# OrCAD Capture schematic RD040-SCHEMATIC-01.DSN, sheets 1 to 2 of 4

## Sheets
1 4: size A3
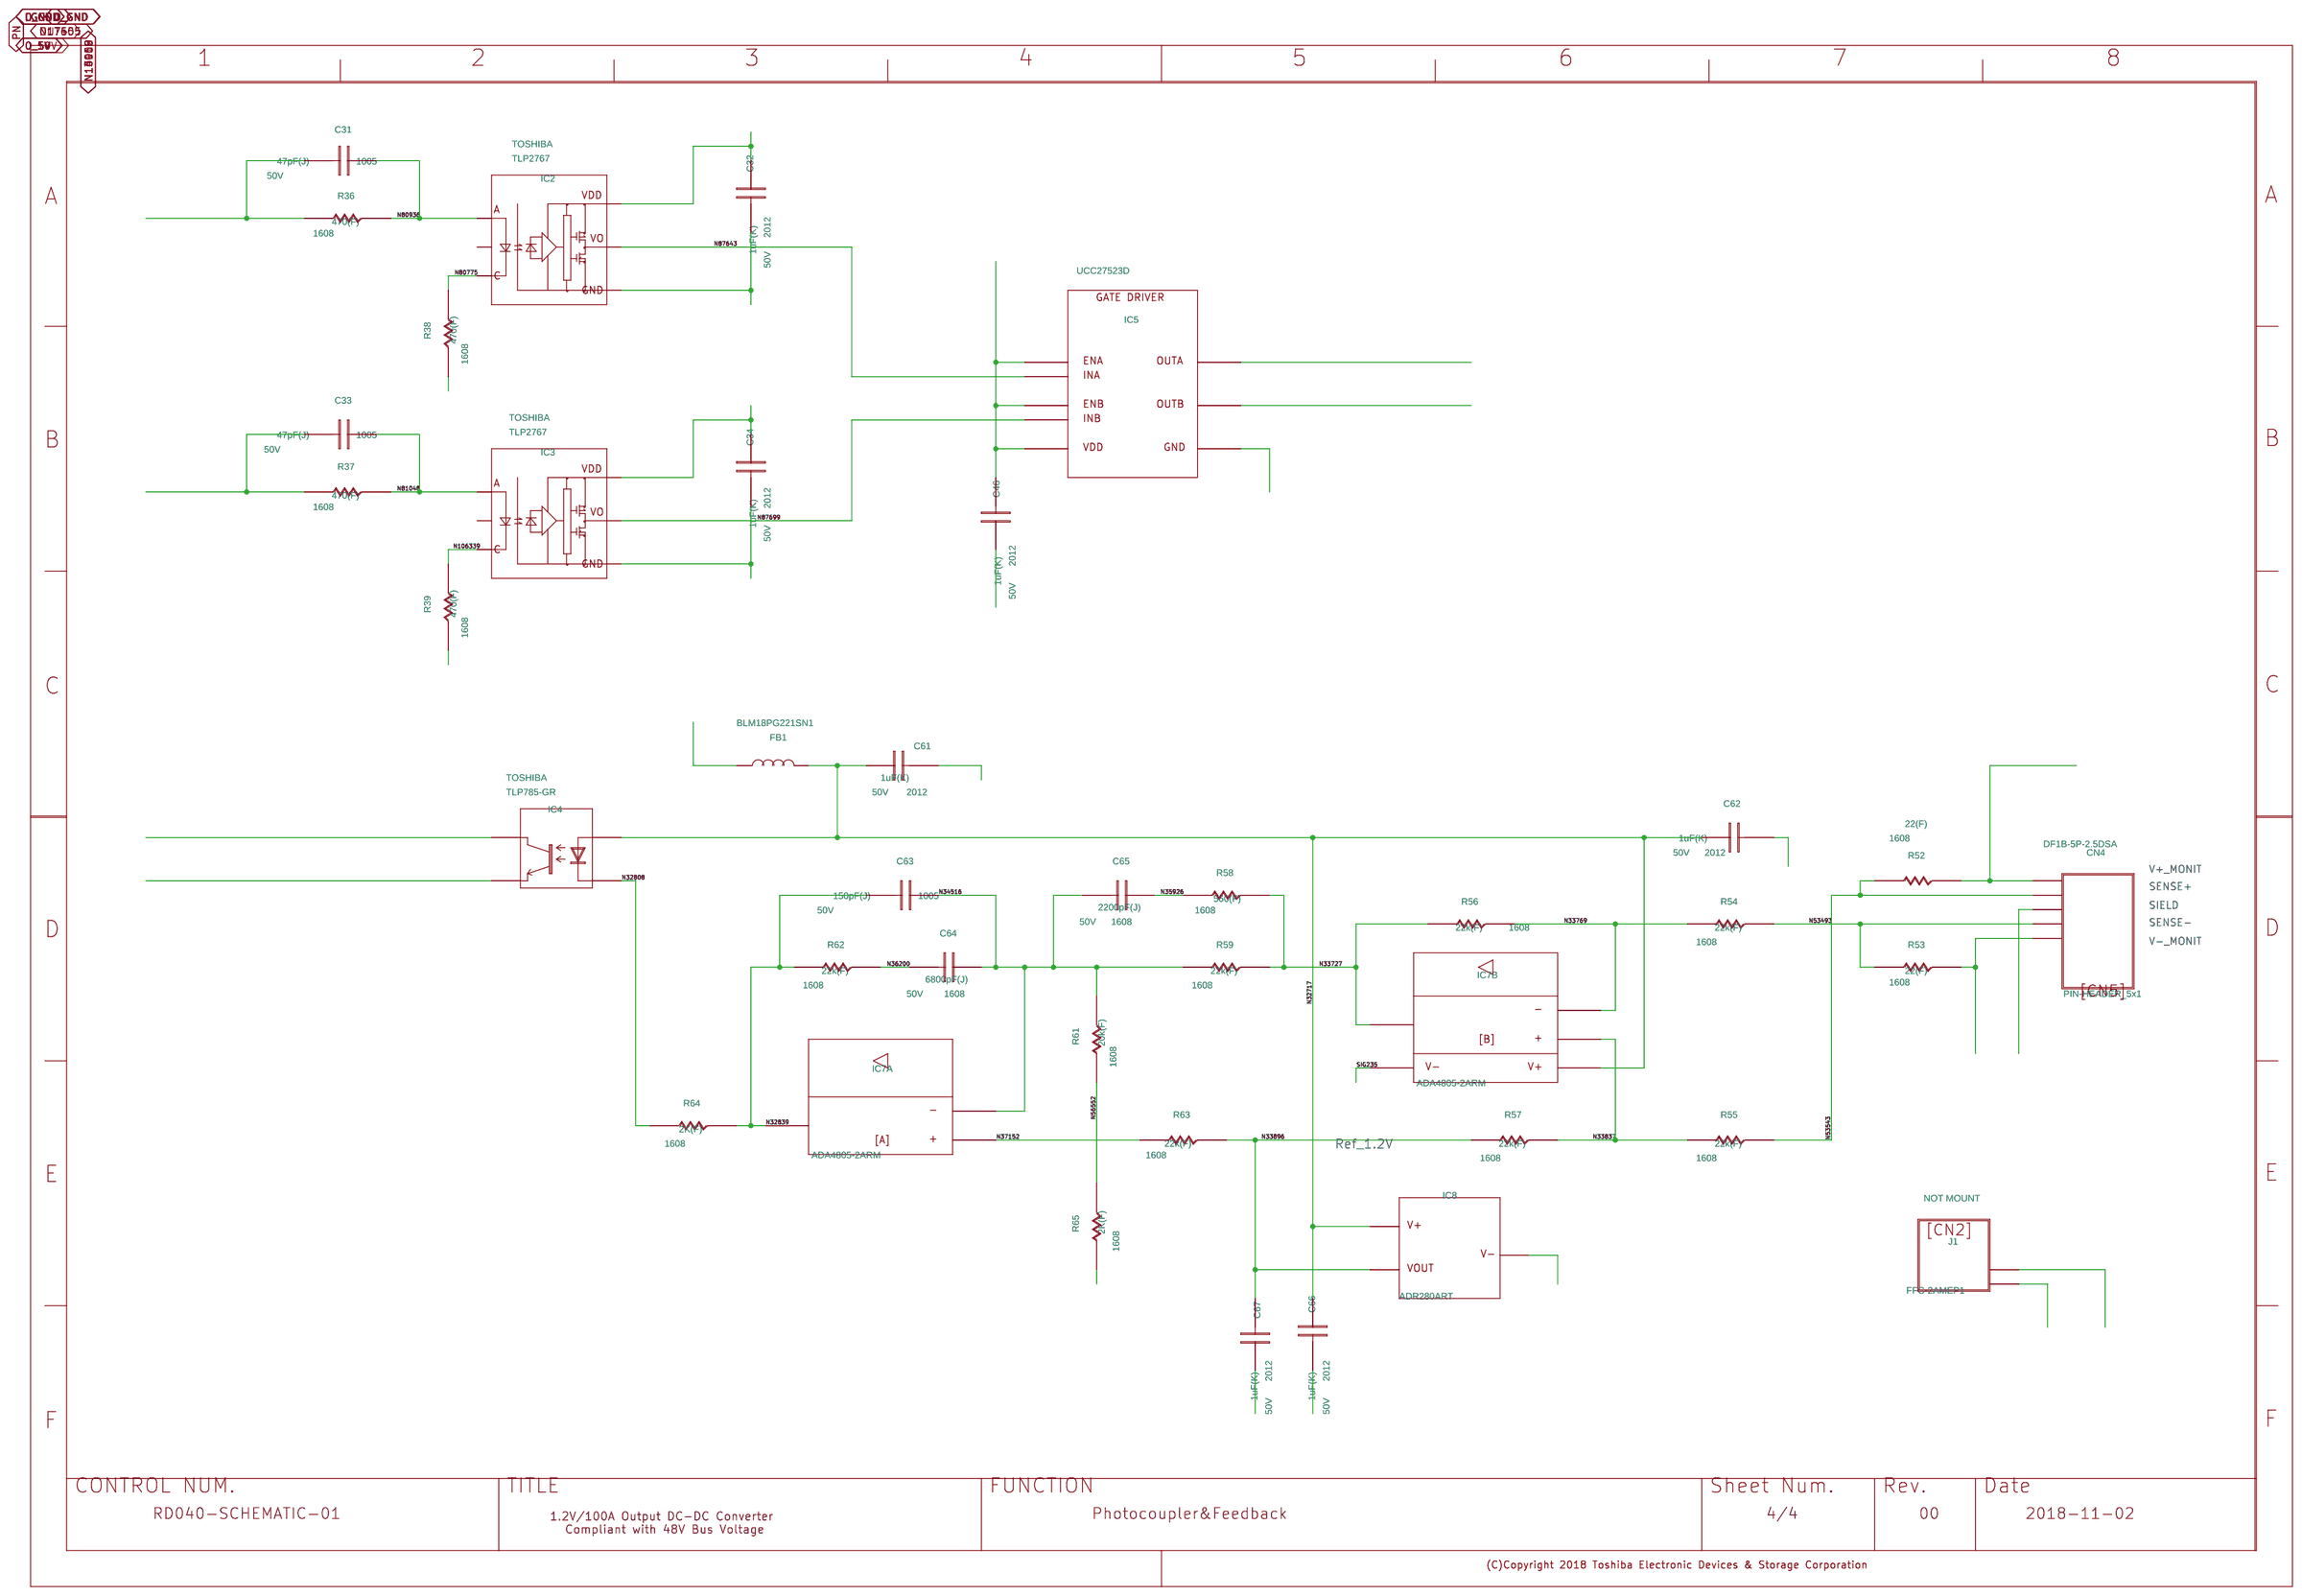
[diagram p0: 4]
2 3: size A3
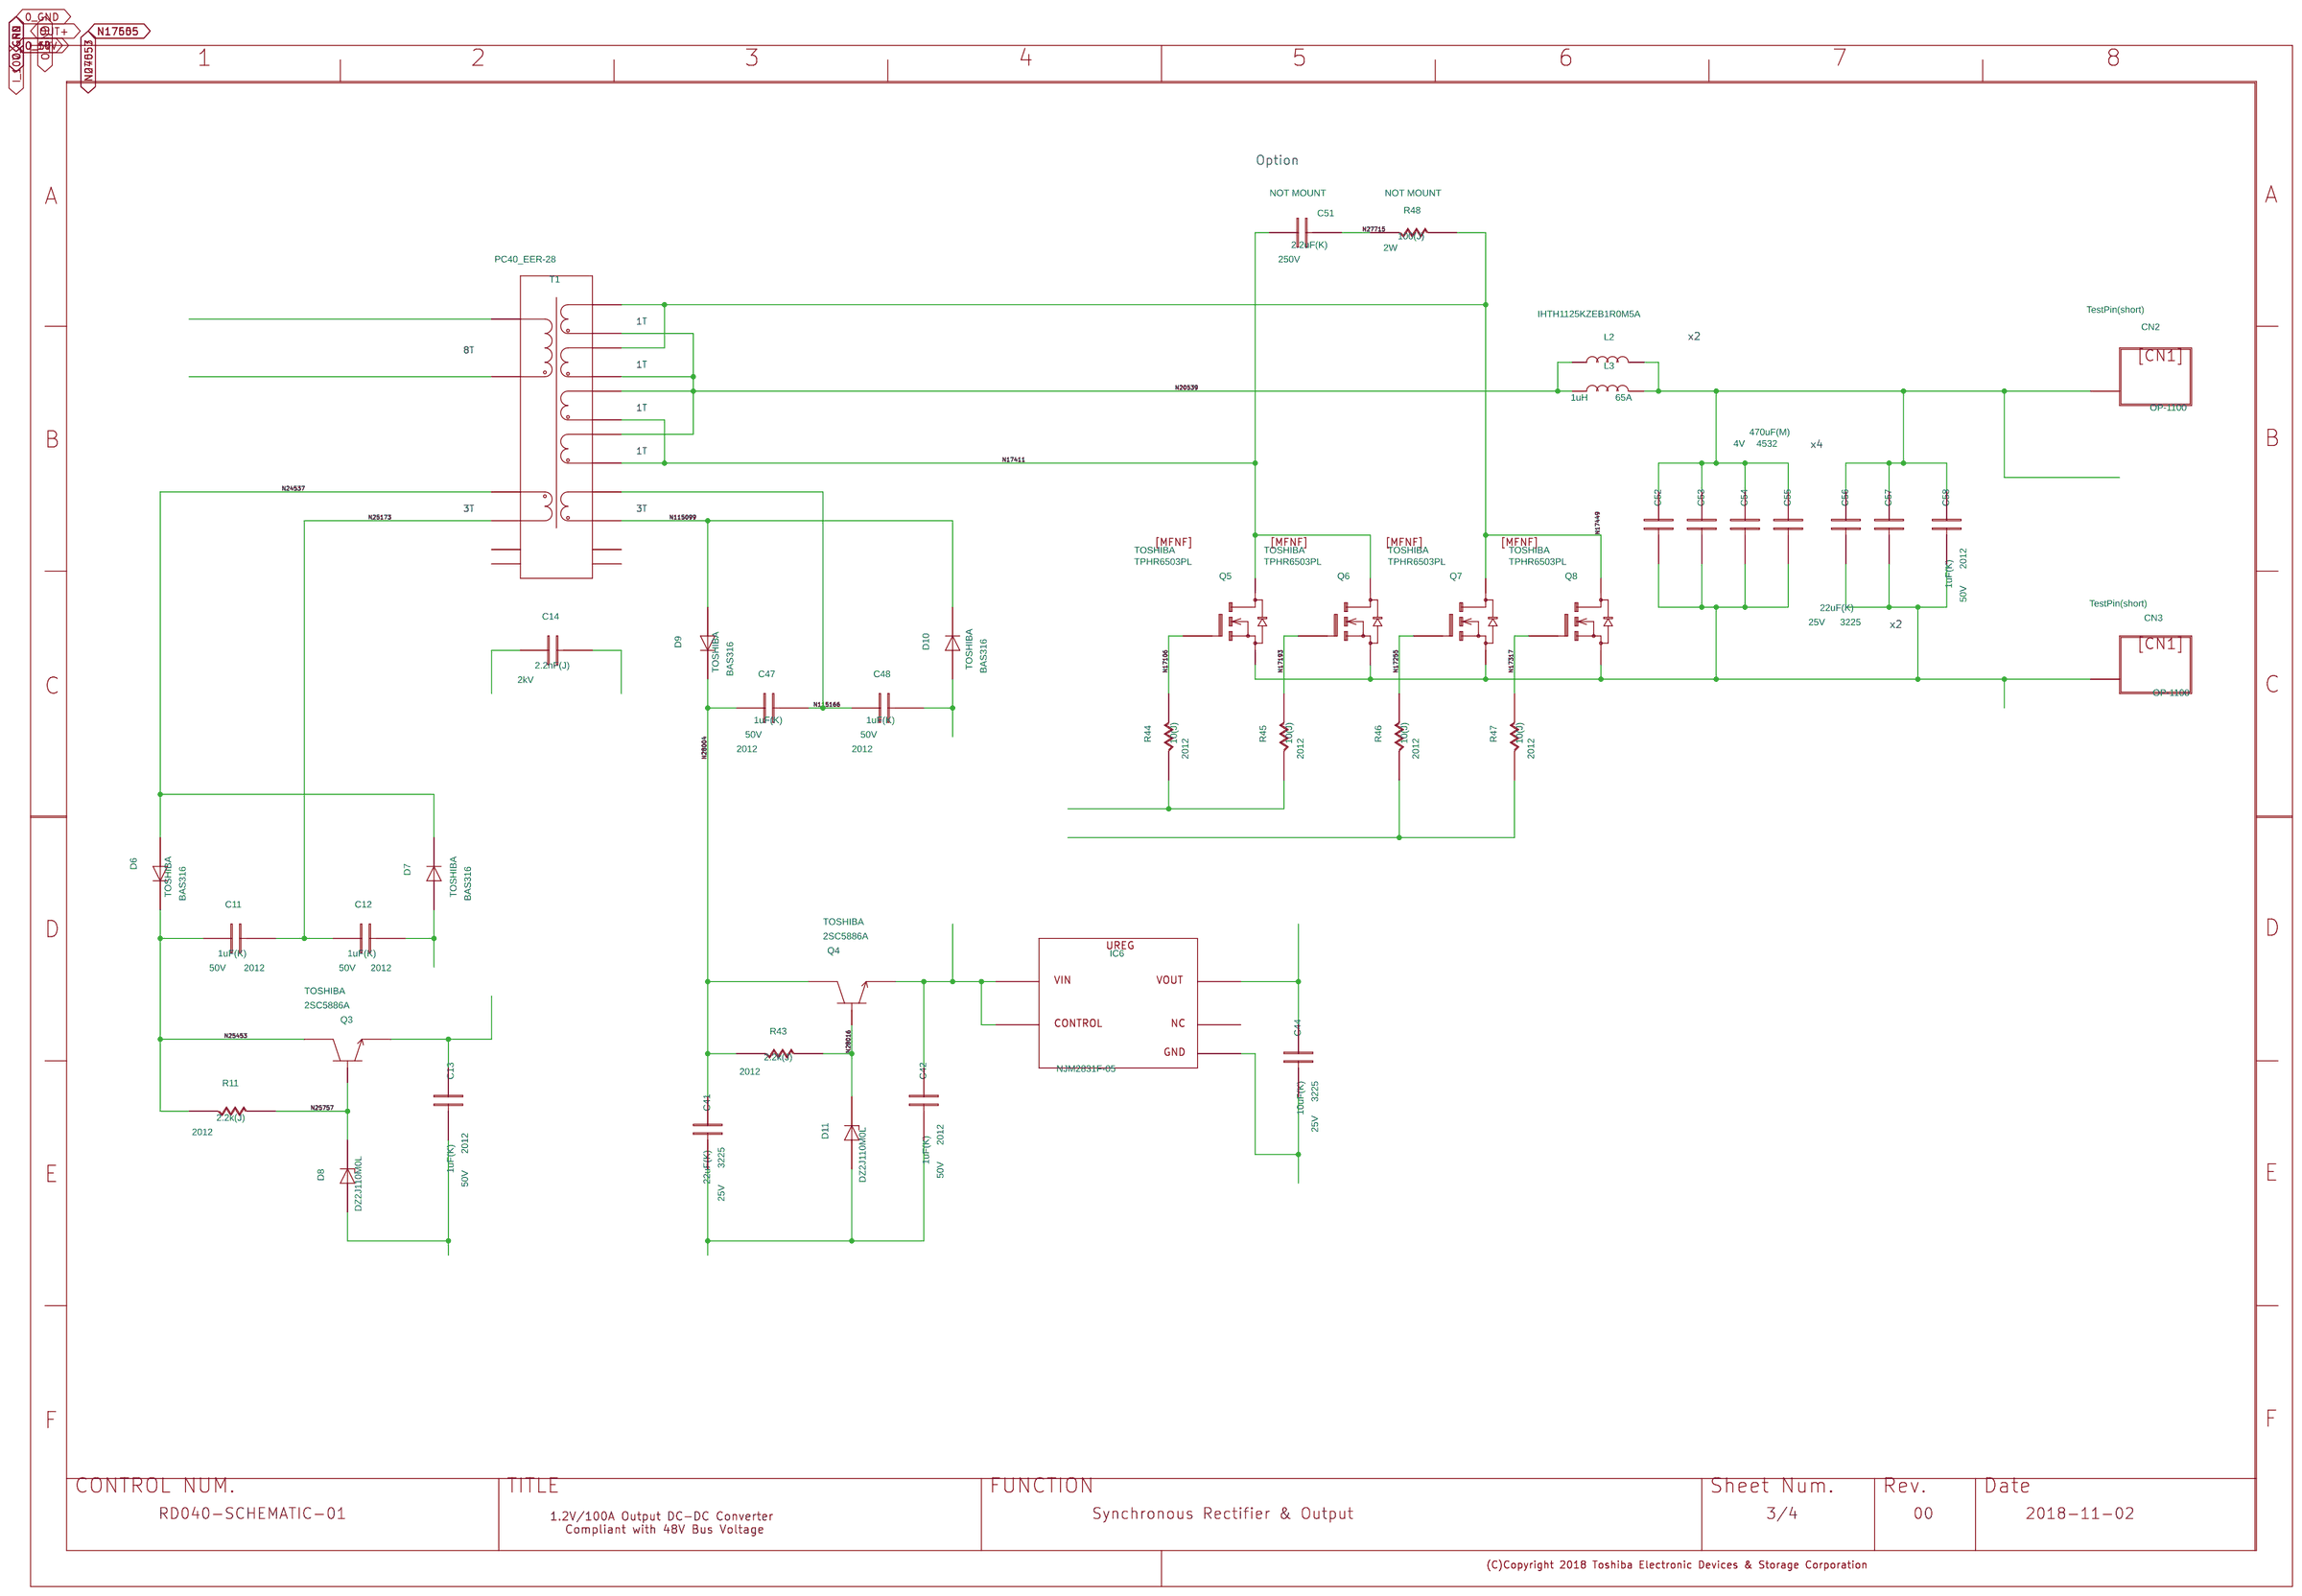
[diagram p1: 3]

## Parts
sheet 3
C11  1uF-K_2012  [CHIP-2012]
C12  1uF-K_2012  [CHIP-2012]
C13  1uF-K_2012  [CHIP-2012]
C14  2200pF-J_2kV  [Radial-2]
C41  22uF-K_3225  [CHIP-3225]
C42  1uF-K_2012  [CHIP-2012]
C44  10uF-K_3225  [CHIP-3225]
C47  1uF-K_2012  [CHIP-2012]
C48  1uF-K_2012  [CHIP-2012]
C51  NM_250V  [Radial-2]
C52  470uF-M_4532  [CHIP-4532]
C53  470uF-M_4532  [CHIP-4532]
C54  470uF-M_4532  [CHIP-4532]
C55  470uF-M_4532  [CHIP-4532]
C56  22uF-K_3225  [CHIP-3225]
C57  22uF-K_3225  [CHIP-3225]
C58  1uF-K_2012  [CHIP-2012]
CN2  OP-1100  [TH-4]
CN3  OP-1100  [TH-4]
D6  BAS316  [CHIP-2012]
D7  BAS316  [CHIP-2012]
D8  DZ2J110M0L  [SC90A]
D9  BAS316  [CHIP-2012]
D10  BAS316  [CHIP-2012]
D11  DZ2J110M0L  [SC90A]
IC6  NJM2831F-05  [SOT23-5]
L2  1uH-M  [RADIAL-2]
L3  1uH-M  [RADIAL-2]
Q3  TRNL
Q4  2SC5886A  [P-MOLD]
Q5  TPHR6503PL  [SO-8]
Q6  TPHR6503PL  [SO-8]
Q7  TPHR6503PL  [SO-8]
Q8  TPHR6503PL  [SO-8]
R11  2k2-J_2012  [CHIP-2012]
R43  2k2-J_2012  [CHIP-2012]
R44  10-J_2012  [CHIP-2012]
R45  10-J_2012  [CHIP-2012]
R46  10-J_2012  [CHIP-2012]
R47  10-J_2012  [CHIP-2012]
R48  NM_2W  [Axial-2]
T1  MAIN-TRANS
U?#1  WAKU_DEF100_2018
sheet 4
C31  47pF-J_1005  [CHIP-1005]
C32  1uF-K_2012  [CHIP-2012]
C33  47pF-J_1005  [CHIP-1005]
C34  1uF-K_2012  [CHIP-2012]
C46  1uF-K_2012  [CHIP-2012]
C61  1uF-K_2012  [CHIP-2012]
C62  1uF-K_2012  [CHIP-2012]
C63  150pF-J_1005  [CHIP-1005]
C64  6800pF-J_1608  [CHIP-1608]
C65  2200pF-J_1608  [CHIP-1608]
C66  1uF-K_2012  [CHIP-2012]
C67  1uF-K_2012  [CHIP-2012]
CN4  DF1B-5P-2.5DSA  [SIP-5]
FB1  BLM18PG221  [CHIP-1608]
IC2  TLP2767  [TSSOP-6]
IC3  TLP2767  [TSSOP-6]
IC4  TLP785-GR  [DIP-4]
IC5  UCC27523D  [SO-8]
IC7  L4805_1  (sections A,B)
IC8  L280
J1  N.M_JUMPER  [SIP-2]
R36  470-F_1608  [CHIP-1608]
R37  470-F_1608  [CHIP-1608]
R38  470-F_1608  [CHIP-1608]
R39  470-F_1608  [CHIP-1608]
R52  22-F_1608  [CHIP-1608]
R53  22-F_1608  [CHIP-1608]
R54  22k-F_1608  [CHIP-1608]
R55  22k-F_1608  [CHIP-1608]
R56  22k-F_1608  [CHIP-1608]
R57  22k-F_1608  [CHIP-1608]
R58  560-F_1608  [CHIP-1608]
R59  22k-F_1608  [CHIP-1608]
R61  20k-F_1608  [CHIP-1608]
R62  22k-F_1608  [CHIP-1608]
R63  22k-F_1608  [CHIP-1608]
R64  2k0-F_1608  [CHIP-1608]
R65  2k0-F_1608  [CHIP-1608]
U?#4  WAKU_DEF100_2018

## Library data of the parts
C11 = C: AUTHOR: w20070dm; COMMENT: Chip-Capacitor(X7R),1uF-K,50V; COMPCOMMENT: 2012; COMPONENTNAME: C_C; COMPONENTTYPE: 4; DATE: 2018/09/12; INSTANCENAME: I25290; MAKER: Murata; NUMBER DEVICES IN PACKAGE: 1; PIN NAMES ROTATE: True; PIN NAMES VISIBLE: False; PIN NUMBERS VISIBLE: False; SAVECOUNT: 1; TIME: 16:59:57; TYPE: GCM21BR71H105K; UPDATEDATE: 2018/09/12; UPDATETIME: 16:59:57; UPDATEUSER: w20070dm; VAL1: 1uF(K); VAL2: 50V; VAL3: GCM21BR71H105K
C12 = C: AUTHOR: w20070dm; COMMENT: Chip-Capacitor(X7R),1uF-K,50V; COMPCOMMENT: 2012; COMPONENTNAME: C_C; COMPONENTTYPE: 4; DATE: 2018/09/12; INSTANCENAME: I25350; MAKER: Murata; NUMBER DEVICES IN PACKAGE: 1; PIN NAMES ROTATE: True; PIN NAMES VISIBLE: False; PIN NUMBERS VISIBLE: False; SAVECOUNT: 1; TIME: 16:59:57; TYPE: GCM21BR71H105K; UPDATEDATE: 2018/09/12; UPDATETIME: 16:59:57; UPDATEUSER: w20070dm; VAL1: 1uF(K); VAL2: 50V; VAL3: GCM21BR71H105K
C13 = C: AUTHOR: w20070dm; COMMENT: Chip-Capacitor(X7R),1uF-K,50V; COMPCOMMENT: 2012; COMPONENTNAME: C_C; COMPONENTTYPE: 4; DATE: 2018/09/12; INSTANCENAME: I29535; MAKER: Murata; NUMBER DEVICES IN PACKAGE: 1; PIN NAMES ROTATE: True; PIN NAMES VISIBLE: False; PIN NUMBERS VISIBLE: False; SAVECOUNT: 1; TIME: 16:59:57; TYPE: GCM21BR71H105K; UPDATEDATE: 2018/09/12; UPDATETIME: 16:59:57; UPDATEUSER: w20070dm; VAL1: 1uF(K); VAL2: 50V; VAL3: GCM21BR71H105K
C14 = C: AUTHOR: w20070dm; COMMENT: Film-Capacitor(PET),2200pF-J,2kVdc; COMPONENTNAME: C_C; COMPONENTTYPE: 4; DATE: 2018/09/12; INSTANCENAME: I20635125; MAKER: Panasonic; NUMBER DEVICES IN PACKAGE: 1; PIN NAMES ROTATE: True; PIN NAMES VISIBLE: False; PIN NUMBERS VISIBLE: False; SAVECOUNT: 1; TIME: 16:59:57; TYPE: ECWH20222JV; UPDATEDATE: 2018/09/12; UPDATETIME: 16:59:57; UPDATEUSER: w20070dm; VAL1: 2.2nF(J); VAL2: 2kV; VAL3: ECWH20222JV
C41 = C: AUTHOR: w20070dm; COMMENT: Chip-Capacitor(X7S),22uF-K,25V; COMPCOMMENT: 3225; COMPONENTNAME: C_C; COMPONENTTYPE: 4; DATE: 2018/09/12; INSTANCENAME: I28285; MAKER: Murata; NUMBER DEVICES IN PACKAGE: 1; PIN NAMES ROTATE: True; PIN NAMES VISIBLE: False; PIN NUMBERS VISIBLE: False; SAVECOUNT: 1; TIME: 16:59:57; TYPE: GRM32ER71E226K; UPDATEDATE: 2018/09/12; UPDATETIME: 16:59:57; UPDATEUSER: w20070dm; VAL1: 22uF(K); VAL2: 25V; VAL3: GRM32ER71E226K
C42 = C: AUTHOR: w20070dm; COMMENT: Chip-Capacitor(X7R),1uF-K,50V; COMPCOMMENT: 2012; COMPONENTNAME: C_C; COMPONENTTYPE: 4; DATE: 2018/09/12; INSTANCENAME: I29753; MAKER: Murata; NUMBER DEVICES IN PACKAGE: 1; PIN NAMES ROTATE: True; PIN NAMES VISIBLE: False; PIN NUMBERS VISIBLE: False; SAVECOUNT: 1; TIME: 16:59:57; TYPE: GCM21BR71H105K; UPDATEDATE: 2018/09/12; UPDATETIME: 16:59:57; UPDATEUSER: w20070dm; VAL1: 1uF(K); VAL2: 50V; VAL3: GCM21BR71H105K
C44 = C: AUTHOR: w20070dm; COMMENT: Chip-Capacitor(X7R),10uF-K,50V; COMPCOMMENT: 3225; COMPONENTNAME: C_C; COMPONENTTYPE: 4; DATE: 2018/09/12; INSTANCENAME: I96322; MAKER: Murata; NUMBER DEVICES IN PACKAGE: 1; PIN NAMES ROTATE: True; PIN NAMES VISIBLE: False; PIN NUMBERS VISIBLE: False; SAVECOUNT: 1; TIME: 16:59:57; TYPE: GCM32ER71H106K; UPDATEDATE: 2018/09/12; UPDATETIME: 16:59:57; UPDATEUSER: w20070dm; VAL1: 10uF(K); VAL2: 25V; VAL3: GCM32ER71E106K
C47 = C: AUTHOR: w20070dm; COMMENT: Chip-Capacitor(X7R),1uF-K,50V; COMPCOMMENT: 2012; COMPONENTNAME: C_C; COMPONENTTYPE: 4; DATE: 2018/09/12; INSTANCENAME: I115041; MAKER: Murata; NUMBER DEVICES IN PACKAGE: 1; PIN NAMES ROTATE: True; PIN NAMES VISIBLE: False; PIN NUMBERS VISIBLE: False; SAVECOUNT: 1; TIME: 16:59:57; TYPE: GCM21BR71H105K; UPDATEDATE: 2018/09/12; UPDATETIME: 16:59:57; UPDATEUSER: w20070dm; VAL1: 1uF(K); VAL2: 50V; VAL3: GCM21BR71H105K
C48 = C: AUTHOR: w20070dm; COMMENT: Chip-Capacitor(X7R),1uF-K,50V; COMPCOMMENT: 2012; COMPONENTNAME: C_C; COMPONENTTYPE: 4; DATE: 2018/09/12; INSTANCENAME: I115081; MAKER: Murata; NUMBER DEVICES IN PACKAGE: 1; PIN NAMES ROTATE: True; PIN NAMES VISIBLE: False; PIN NUMBERS VISIBLE: False; SAVECOUNT: 1; TIME: 16:59:57; TYPE: GCM21BR71H105K; UPDATEDATE: 2018/09/12; UPDATETIME: 16:59:57; UPDATEUSER: w20070dm; VAL1: 1uF(K); VAL2: 50V; VAL3: GCM21BR71H105K
C51 = C: AUTHOR: w20070dm; COMMENT: Film-Capacitor(PET),2.2uF-K,250V; COMPONENTNAME: C_C; COMPONENTTYPE: 4; DATE: 2018/09/12; INSTANCENAME: I27743; MAKER: Panasonic; NOTMOUNT: NOT MOUNT; NUMBER DEVICES IN PACKAGE: 1; PIN NAMES ROTATE: True; PIN NAMES VISIBLE: False; PIN NUMBERS VISIBLE: False; SAVECOUNT: 1; TIME: 16:59:57; TYPE: ECQE2225KB; UPDATEDATE: 2018/09/12; UPDATETIME: 16:59:57; UPDATEUSER: w20070dm; VAL1: 2.2uF(K); VAL2: 250V; VAL3: ECQE2225KB
C52 = C: AUTHOR: w20070dm; COMMENT: Chip-Capacitor(X5R),470uF-M,4V; COMPCOMMENT: 4532; COMPONENTNAME: C_C; COMPONENTTYPE: 4; DATE: 2018/09/12; INSTANCENAME: I19086; MAKER: Taiyo-Yuden; NUMBER DEVICES IN PACKAGE: 1; PIN NAMES ROTATE: True; PIN NAMES VISIBLE: False; PIN NUMBERS VISIBLE: False; SAVECOUNT: 1; TIME: 16:59:57; TYPE: AMK432BJ477MM; UPDATEDATE: 2018/09/12; UPDATETIME: 16:59:57; UPDATEUSER: w20070dm; VAL1: 470uF(M); VAL2: 4V; VAL3: AMK432BJ477MM
C53 = C: AUTHOR: w20070dm; COMMENT: Chip-Capacitor(X5R),470uF-M,4V; COMPCOMMENT: 4532; COMPONENTNAME: C_C; COMPONENTTYPE: 4; DATE: 2018/09/12; INSTANCENAME: I19062; MAKER: Taiyo-Yuden; NUMBER DEVICES IN PACKAGE: 1; PIN NAMES ROTATE: True; PIN NAMES VISIBLE: False; PIN NUMBERS VISIBLE: False; SAVECOUNT: 1; TIME: 16:59:57; TYPE: AMK432BJ477MM; UPDATEDATE: 2018/09/12; UPDATETIME: 16:59:57; UPDATEUSER: w20070dm; VAL1: 470uF(M); VAL2: 4V; VAL3: AMK432BJ477MM
C54 = C: AUTHOR: w20070dm; COMMENT: Chip-Capacitor(X5R),470uF-M,4V; COMPCOMMENT: 4532; COMPONENTNAME: C_C; COMPONENTTYPE: 4; DATE: 2018/09/12; INSTANCENAME: I19038; MAKER: Taiyo-Yuden; NUMBER DEVICES IN PACKAGE: 1; PIN NAMES ROTATE: True; PIN NAMES VISIBLE: False; PIN NUMBERS VISIBLE: False; SAVECOUNT: 1; TIME: 16:59:57; TYPE: AMK432BJ477MM; UPDATEDATE: 2018/09/12; UPDATETIME: 16:59:57; UPDATEUSER: w20070dm; VAL1: 470uF(M); VAL2: 4V; VAL3: AMK432BJ477MM
C55 = C: AUTHOR: w20070dm; COMMENT: Chip-Capacitor(X5R),470uF-M,4V; COMPCOMMENT: 4532; COMPONENTNAME: C_C; COMPONENTTYPE: 4; DATE: 2018/09/12; INSTANCENAME: I18954; MAKER: Taiyo-Yuden; NUMBER DEVICES IN PACKAGE: 1; PIN NAMES ROTATE: True; PIN NAMES VISIBLE: False; PIN NUMBERS VISIBLE: False; SAVECOUNT: 1; TIME: 16:59:57; TYPE: AMK432BJ477MM; UPDATEDATE: 2018/09/12; UPDATETIME: 16:59:57; UPDATEUSER: w20070dm; VAL1: 470uF(M); VAL2: 4V; VAL3: AMK432BJ477MM
C56 = C: AUTHOR: w20070dm; COMMENT: Chip-Capacitor(X7S),22uF-K,25V; COMPCOMMENT: 3225; COMPONENTNAME: C_C; COMPONENTTYPE: 4; DATE: 2018/09/12; INSTANCENAME: I18705; MAKER: Murata; NUMBER DEVICES IN PACKAGE: 1; PIN NAMES ROTATE: True; PIN NAMES VISIBLE: False; PIN NUMBERS VISIBLE: False; SAVECOUNT: 1; TIME: 16:59:57; TYPE: GRM32ER71E226K; UPDATEDATE: 2018/09/12; UPDATETIME: 16:59:57; UPDATEUSER: w20070dm; VAL1: 22uF(K); VAL2: 25V; VAL3: GRM32ER71E226K
C57 = C: AUTHOR: w20070dm; COMMENT: Chip-Capacitor(X7S),22uF-K,25V; COMPCOMMENT: 3225; COMPONENTNAME: C_C; COMPONENTTYPE: 4; DATE: 2018/09/12; INSTANCENAME: I19014; MAKER: Murata; NUMBER DEVICES IN PACKAGE: 1; PIN NAMES ROTATE: True; PIN NAMES VISIBLE: False; PIN NUMBERS VISIBLE: False; SAVECOUNT: 1; TIME: 16:59:57; TYPE: GRM32ER71E226K; UPDATEDATE: 2018/09/12; UPDATETIME: 16:59:57; UPDATEUSER: w20070dm; VAL1: 22uF(K); VAL2: 25V; VAL3: GRM32ER71E226K
C58 = C: AUTHOR: w20070dm; COMMENT: Chip-Capacitor(X7R),1uF-K,50V; COMPCOMMENT: 2012; COMPONENTNAME: C_C; COMPONENTTYPE: 4; DATE: 2018/09/12; INSTANCENAME: I18657; MAKER: Murata; NUMBER DEVICES IN PACKAGE: 1; PIN NAMES ROTATE: True; PIN NAMES VISIBLE: False; PIN NUMBERS VISIBLE: False; SAVECOUNT: 1; TIME: 16:59:57; TYPE: GCM21BR71H105K; UPDATEDATE: 2018/09/12; UPDATETIME: 16:59:57; UPDATEUSER: w20070dm; VAL1: 1uF(K); VAL2: 50V; VAL3: GCM21BR71H105K
CN2 = CN1: AUTHOR: w20070dm; COMMENT: Terminal-Block(PCB_1P,135A1000V); COMPCOMMENT: TestPin(short); COMPONENTNAME: TestPin(short)_TestPin(short).Normal_package; COMPONENTTYPE: 4; DATE: 2018/09/12; FUNCTION: TestPin(short)_TestPin(short).Normal_package; INSTANCENAME: I22103497; MAKER: Osada; NUMBER DEVICES IN PACKAGE: 1; PARTNAME: TestPin(short); PIN NAMES ROTATE: True; PIN NAMES VISIBLE: False; PIN NUMBERS VISIBLE: False; SAVECOUNT: 1; TIME: 16:59:57; UPDATEDATE: 2018/09/12; UPDATETIME: 16:59:57; UPDATEUSER: w20070dm
CN3 = CN1: AUTHOR: w20070dm; COMMENT: Terminal-Block(PCB_1P,135A1000V); COMPCOMMENT: TestPin(short); COMPONENTNAME: TestPin(short)_TestPin(short).Normal_package; COMPONENTTYPE: 4; DATE: 2018/09/12; FUNCTION: TestPin(short)_TestPin(short).Normal_package; INSTANCENAME: I23904; MAKER: Osada; NUMBER DEVICES IN PACKAGE: 1; PARTNAME: TestPin(short); PIN NAMES ROTATE: True; PIN NAMES VISIBLE: False; PIN NUMBERS VISIBLE: False; SAVECOUNT: 1; TIME: 16:59:57; UPDATEDATE: 2018/09/12; UPDATETIME: 16:59:57; UPDATEUSER: w20070dm
D6 = D: COMMENT: SW-Diode(100V250mA); COMPONENTNAME: DIODE_DIODE; COMPONENTTYPE: 4; INSTANCENAME: I24616; MAKER: Toshiba; NUMBER DEVICES IN PACKAGE: 1; PARTNAME: DIODE; PIN NAMES ROTATE: True; PIN NAMES VISIBLE: False; PIN NUMBERS VISIBLE: False; USERCOMPTEXT3: TOSHIBA
D7 = D: COMMENT: SW-Diode(100V250mA); COMPONENTNAME: DIODE_DIODE; COMPONENTTYPE: 4; INSTANCENAME: I24652; MAKER: Toshiba; NUMBER DEVICES IN PACKAGE: 1; PARTNAME: DIODE; PIN NAMES ROTATE: True; PIN NAMES VISIBLE: False; PIN NUMBERS VISIBLE: False; USERCOMPTEXT3: TOSHIBA
D8 = ZD: COMMENT: Zener-Diode(11V200mW); COMPONENTNAME: DIODE ZENER_DIODE ZENER; COMPONENTTYPE: 4; INSTANCENAME: I20621212; MAKER: Panasonic; NUMBER DEVICES IN PACKAGE: 1; PARTNAME: DIODE ZENER; PIN NAMES ROTATE: True; PIN NAMES VISIBLE: False; PIN NUMBERS VISIBLE: False
D9 = D: COMMENT: SW-Diode(100V250mA); COMPONENTNAME: DIODE_DIODE; COMPONENTTYPE: 4; INSTANCENAME: I30564; MAKER: Toshiba; NUMBER DEVICES IN PACKAGE: 1; PARTNAME: DIODE; PIN NAMES ROTATE: True; PIN NAMES VISIBLE: False; PIN NUMBERS VISIBLE: False; USERCOMPTEXT3: TOSHIBA
D10 = D: COMMENT: SW-Diode(100V250mA); COMPONENTNAME: DIODE_DIODE; COMPONENTTYPE: 4; INSTANCENAME: I30540; MAKER: Toshiba; NUMBER DEVICES IN PACKAGE: 1; PARTNAME: DIODE; PIN NAMES ROTATE: True; PIN NAMES VISIBLE: False; PIN NUMBERS VISIBLE: False; USERCOMPTEXT3: TOSHIBA
D11 = ZD: COMMENT: Zener-Diode(11V200mW); COMPONENTNAME: DIODE ZENER_DIODE ZENER; COMPONENTTYPE: 4; INSTANCENAME: I22176; MAKER: Panasonic; NUMBER DEVICES IN PACKAGE: 1; PARTNAME: DIODE ZENER; PIN NAMES ROTATE: True; PIN NAMES VISIBLE: False; PIN NUMBERS VISIBLE: False
IC6 = L2831F: COMMENT: LDO(fixed_5V,100mA); COMPONENTNAME: NJM2831F_NJM2831F.Normal_package; COMPONENTTYPE: 4; FUNCTION: NJM2831F_NJM2831F.Normal_package; INSTANCENAME: I111366; MAKER: NJR; NUMBER DEVICES IN PACKAGE: 1; PARTNAME: NJM2831F; PIN NAMES ROTATE: True; PIN NAMES VISIBLE: True; PIN NUMBERS VISIBLE: True
L2 = L: AUTHOR: w20070dm; COMMENT: Inductor(1.0uH65A); COMPONENTNAME: INDUCTOR_INDUCTOR; COMPONENTTYPE: 4; DATE: 2018/09/12; INSTANCENAME: I18633; MAKER: Vishay; NUMBER DEVICES IN PACKAGE: 1; ORDER: 0; PARTNAME: INDUCTOR; PIN NAMES ROTATE: True; PIN NAMES VISIBLE: False; PIN NUMBERS VISIBLE: False; SAVECOUNT: 1; TIME: 16:59:57; TYPE: IHTH1125KZEB1R0M5A; UPDATEDATE: 2018/09/12; UPDATETIME: 16:59:57; UPDATEUSER: w20070dm; VAL1: 1uH; VAL2: 65A; VAL3: IHTH1125KZEB1R0M5A
L3 = L: AUTHOR: w20070dm; COMMENT: Inductor(1.0uH65A); COMPONENTNAME: INDUCTOR_INDUCTOR; COMPONENTTYPE: 4; DATE: 2018/09/12; INSTANCENAME: I21382; MAKER: Vishay; NUMBER DEVICES IN PACKAGE: 1; ORDER: 0; PARTNAME: INDUCTOR; PIN NAMES ROTATE: True; PIN NAMES VISIBLE: False; PIN NUMBERS VISIBLE: False; SAVECOUNT: 1; TIME: 16:59:57; TYPE: IHTH1125KZEB1R0M5A; UPDATEDATE: 2018/09/12; UPDATETIME: 16:59:57; UPDATEUSER: w20070dm; VAL1: 1uH; VAL2: 65A; VAL3: IHTH1125KZEB1R0M5A
Q3 = TRNL: COMPONENTTYPE: 4; PARTNAME: NPNBCE; USERCOMPTEXT3: TOSHIBA; VAL3: 2SC5886A
Q4 = TRNL: COMMENT: Bipolar-Transister(npn,50V_5A); COMPONENTNAME: NPN BCE_NPN BCE.Normal_package; COMPONENTTYPE: 4; FUNCTION: NPN BCE_NPN BCE.Normal_package; INSTANCENAME: I28100; MAKER: Toshiba; NUMBER DEVICES IN PACKAGE: 1; ORDER: 0; PARTNAME: NPN BCE; PIN NAMES ROTATE: True; PIN NAMES VISIBLE: False; PIN NUMBERS VISIBLE: False; USERCOMPTEXT3: TOSHIBA
Q5 = MFNF: AUTHOR: w20070dm; COMMENT: MOS-FET(n-ch,30V150A); COMPONENTNAME: MOSFET_N(D)_MOSFET_N(D).Normal_package; COMPONENTTYPE: 4; DATE: 2018/09/12; FUNCTION: MOSFET_N(D)_MOSFET_N(D).Normal_package; INSTANCENAME: I18597; MAKER: Toshiba; NUMBER DEVICES IN PACKAGE: 1; PARTNAME: MOSFET_N(D); PIN NAMES ROTATE: True; PIN NAMES VISIBLE: False; PIN NUMBERS VISIBLE: True; TIME: 16:59:57; UPDATEDATE: 2018/09/12; UPDATETIME: 16:59:57; UPDATEUSER: w20070dm; USERCOMPTEXT3: TOSHIBA
Q6 = MFNF: AUTHOR: w20070dm; COMMENT: MOS-FET(n-ch,30V150A); COMPONENTNAME: MOSFET_N(D)_MOSFET_N(D).Normal_package; COMPONENTTYPE: 4; DATE: 2018/09/12; FUNCTION: MOSFET_N(D)_MOSFET_N(D).Normal_package; INSTANCENAME: I18557; MAKER: Toshiba; NUMBER DEVICES IN PACKAGE: 1; PARTNAME: MOSFET_N(D); PIN NAMES ROTATE: True; PIN NAMES VISIBLE: False; PIN NUMBERS VISIBLE: True; TIME: 16:59:57; UPDATEDATE: 2018/09/12; UPDATETIME: 16:59:57; UPDATEUSER: w20070dm; USERCOMPTEXT3: TOSHIBA
Q7 = MFNF: AUTHOR: w20070dm; COMMENT: MOS-FET(n-ch,30V150A); COMPONENTNAME: MOSFET_N(D)_MOSFET_N(D).Normal_package; COMPONENTTYPE: 4; DATE: 2018/09/12; FUNCTION: MOSFET_N(D)_MOSFET_N(D).Normal_package; INSTANCENAME: I18517; MAKER: Toshiba; NUMBER DEVICES IN PACKAGE: 1; PARTNAME: MOSFET_N(D); PIN NAMES ROTATE: True; PIN NAMES VISIBLE: False; PIN NUMBERS VISIBLE: True; TIME: 16:59:57; UPDATEDATE: 2018/09/12; UPDATETIME: 16:59:57; UPDATEUSER: w20070dm; USERCOMPTEXT3: TOSHIBA
Q8 = MFNF: AUTHOR: w20070dm; COMMENT: MOS-FET(n-ch,30V150A); COMPONENTNAME: MOSFET_N(D)_MOSFET_N(D).Normal_package; COMPONENTTYPE: 4; DATE: 2018/09/12; FUNCTION: MOSFET_N(D)_MOSFET_N(D).Normal_package; INSTANCENAME: I17285; MAKER: Toshiba; NUMBER DEVICES IN PACKAGE: 1; PARTNAME: MOSFET_N(D); PIN NAMES ROTATE: True; PIN NAMES VISIBLE: False; PIN NUMBERS VISIBLE: True; TIME: 16:59:57; UPDATEDATE: 2018/09/12; UPDATETIME: 16:59:57; UPDATEUSER: w20070dm; USERCOMPTEXT3: TOSHIBA
R11 = R: AUTHOR: w20070dm; COMMENT: Chip-Resister(anti-surge),2k2-J,0.4W; COMPCOMMENT: 2012; COMPONENTNAME: R_R; COMPONENTTYPE: 4; DATE: 2018/09/12; INSTANCENAME: I25781; MAKER: ROHM; NUMBER DEVICES IN PACKAGE: 1; PIN NAMES ROTATE: True; PIN NAMES VISIBLE: False; PIN NUMBERS VISIBLE: False; SAVECOUNT: 1; TIME: 16:59:57; TYPE: ESR10EZPJ222; UPDATEDATE: 2018/09/12; UPDATETIME: 16:59:57; UPDATEUSER: w20070dm; VAL1: 2.2k(J); VAL2: 0.4W; VAL3: ESR10EZPJ222
R43 = R: AUTHOR: w20070dm; COMMENT: Chip-Resister(anti-surge),2k2-J,0.4W; COMPCOMMENT: 2012; COMPONENTNAME: R_R; COMPONENTTYPE: 4; DATE: 2018/09/12; INSTANCENAME: I28040; MAKER: ROHM; NUMBER DEVICES IN PACKAGE: 1; PIN NAMES ROTATE: True; PIN NAMES VISIBLE: False; PIN NUMBERS VISIBLE: False; SAVECOUNT: 1; TIME: 16:59:57; TYPE: ESR10EZPJ222; UPDATEDATE: 2018/09/12; UPDATETIME: 16:59:57; UPDATEUSER: w20070dm; VAL1: 2.2k(J); VAL2: 0.4W; VAL3: ESR10EZPJ222
R44 = R: AUTHOR: w20070dm; COMMENT: Chip-Resister(anti-surge),10ohm-J,0.4W; COMPCOMMENT: 2012; COMPONENTNAME: R_R; COMPONENTTYPE: 4; DATE: 2018/09/12; INSTANCENAME: I17028; MAKER: ROHM; NUMBER DEVICES IN PACKAGE: 1; PIN NAMES ROTATE: True; PIN NAMES VISIBLE: False; PIN NUMBERS VISIBLE: False; SAVECOUNT: 1; TIME: 16:59:57; TYPE: ESR10EZPJ100; UPDATEDATE: 2018/09/12; UPDATETIME: 16:59:57; UPDATEUSER: w20070dm; VAL1: 10(J); VAL2: 0.4W; VAL3: ESR10EZPJ100
R45 = R: AUTHOR: w20070dm; COMMENT: Chip-Resister(anti-surge),10ohm-J,0.4W; COMPCOMMENT: 2012; COMPONENTNAME: R_R; COMPONENTTYPE: 4; DATE: 2018/09/12; INSTANCENAME: I17185; MAKER: ROHM; NUMBER DEVICES IN PACKAGE: 1; PIN NAMES ROTATE: True; PIN NAMES VISIBLE: False; PIN NUMBERS VISIBLE: False; SAVECOUNT: 1; TIME: 16:59:57; TYPE: ESR10EZPJ100; UPDATEDATE: 2018/09/12; UPDATETIME: 16:59:57; UPDATEUSER: w20070dm; VAL1: 10(J); VAL2: 0.4W; VAL3: ESR10EZPJ100
R46 = R: AUTHOR: w20070dm; COMMENT: Chip-Resister(anti-surge),10ohm-J,0.4W; COMPCOMMENT: 2012; COMPONENTNAME: R_R; COMPONENTTYPE: 4; DATE: 2018/09/12; INSTANCENAME: I17247; MAKER: ROHM; NUMBER DEVICES IN PACKAGE: 1; PIN NAMES ROTATE: True; PIN NAMES VISIBLE: False; PIN NUMBERS VISIBLE: False; SAVECOUNT: 1; TIME: 16:59:57; TYPE: ESR10EZPJ100; UPDATEDATE: 2018/09/12; UPDATETIME: 16:59:57; UPDATEUSER: w20070dm; VAL1: 10(J); VAL2: 0.4W; VAL3: ESR10EZPJ100
R47 = R: AUTHOR: w20070dm; COMMENT: Chip-Resister(anti-surge),10ohm-J,0.4W; COMPCOMMENT: 2012; COMPONENTNAME: R_R; COMPONENTTYPE: 4; DATE: 2018/09/12; INSTANCENAME: I17309; MAKER: ROHM; NUMBER DEVICES IN PACKAGE: 1; PIN NAMES ROTATE: True; PIN NAMES VISIBLE: False; PIN NUMBERS VISIBLE: False; SAVECOUNT: 1; TIME: 16:59:57; TYPE: ESR10EZPJ100; UPDATEDATE: 2018/09/12; UPDATETIME: 16:59:57; UPDATEUSER: w20070dm; VAL1: 10(J); VAL2: 0.4W; VAL3: ESR10EZPJ100
R48 = R: AUTHOR: w20070dm; COMMENT: Metal-Film-Resister,100ohm-J,2W; COMPONENTNAME: R_R; COMPONENTTYPE: 4; DATE: 2018/09/12; INSTANCENAME: I27703; MAKER: ROHM; NOTMOUNT: NOT MOUNT; NUMBER DEVICES IN PACKAGE: 1; PIN NAMES ROTATE: True; PIN NAMES VISIBLE: False; PIN NUMBERS VISIBLE: False; SAVECOUNT: 1; TIME: 16:59:57; TYPE: MOS2CT52A101J; UPDATEDATE: 2018/09/12; UPDATETIME: 16:59:57; UPDATEUSER: w20070dm; VAL1: 100(J); VAL2: 2W; VAL3: MOS2CT52A101J
T1 = PC40-EER28: COMMENT: Transformer(EER28.5,12T:2T:1T:1T:2T); COMPONENTNAME: AF-TRANS(5A)_AF-TRANS(5A).Normal_package; COMPONENTTYPE: 4; FUNCTION: AF-TRANS(5A)_AF-TRANS(5A).Normal_package; INSTANCENAME: I20627; MAKER: TDK; NUMBER DEVICES IN PACKAGE: 1; ORDER: 0; PARTNAME: AF-TRANS(5A); PIN NAMES ROTATE: True; PIN NAMES VISIBLE: False; PIN NUMBERS VISIBLE: True; TYPE: PC40_EER-28; VAL1: PC40_EER-28; VAL3: PC40_EER-28
U?#1 = WAKU_DEF100_2018: COMPONENTTYPE: 2; DATE: 2018-11-02; DRAWINGNUMBER: RD040-SCHEMATIC-01; FUNCTION: Synchronous Rectifier & Output; REVISION: 00; SAVEAREA0: -45080,-4508,463680,304612; SHEETNUMBER: 3/4; TIME: 13:53:51; TITLE: 1.2V/100A Output DC-DC Converter / Compliant with 48V Bus Voltage; UPDATEDATE: 2018/11/05; UPDATETIME: 09:58:42
C31 = C: AUTHOR: w20070dm; COMMENT: Chip-Capasitor(CH0),47pF-J,50V; COMPCOMMENT: 1005; COMPONENTNAME: C_C; COMPONENTTYPE: 4; DATE: 2018/09/12; INSTANCENAME: I80858; MAKER: MURATA; NUMBER DEVICES IN PACKAGE: 1; PIN NAMES ROTATE: True; PIN NAMES VISIBLE: False; PIN NUMBERS VISIBLE: False; SAVECOUNT: 1; TIME: 16:59:57; TYPE: GRM1552C1H470J; UPDATEDATE: 2018/09/12; UPDATETIME: 16:59:57; UPDATEUSER: w20070dm; VAL1: 47pF(J); VAL2: 50V; VAL3: GRM1552C1H470J
C32 = C: AUTHOR: w20070dm; COMMENT: Chip-Capacitor(X7R),1uF-K,50V; COMPCOMMENT: 2012; COMPONENTNAME: C_C; COMPONENTTYPE: 4; DATE: 2018/09/12; INSTANCENAME: I91091; MAKER: Murata; NUMBER DEVICES IN PACKAGE: 1; PIN NAMES ROTATE: True; PIN NAMES VISIBLE: False; PIN NUMBERS VISIBLE: False; SAVECOUNT: 1; TIME: 16:59:57; TYPE: GCM21BR71H105K; UPDATEDATE: 2018/09/12; UPDATETIME: 16:59:57; UPDATEUSER: w20070dm; VAL1: 1uF(K); VAL2: 50V; VAL3: GCM21BR71H105K
C33 = C: AUTHOR: w20070dm; COMMENT: Chip-Capasitor(CH0),47pF-J,50V; COMPCOMMENT: 1005; COMPONENTNAME: C_C; COMPONENTTYPE: 4; DATE: 2018/09/12; INSTANCENAME: I81096; MAKER: MURATA; NUMBER DEVICES IN PACKAGE: 1; PIN NAMES ROTATE: True; PIN NAMES VISIBLE: False; PIN NUMBERS VISIBLE: False; SAVECOUNT: 1; TIME: 16:59:57; TYPE: GRM1552C1H470J; UPDATEDATE: 2018/09/12; UPDATETIME: 16:59:57; UPDATEUSER: w20070dm; VAL1: 47pF(J); VAL2: 50V; VAL3: GRM1552C1H470J
C34 = C: AUTHOR: w20070dm; COMMENT: Chip-Capacitor(X7R),1uF-K,50V; COMPCOMMENT: 2012; COMPONENTNAME: C_C; COMPONENTTYPE: 4; DATE: 2018/09/12; INSTANCENAME: I91367; MAKER: Murata; NUMBER DEVICES IN PACKAGE: 1; PIN NAMES ROTATE: True; PIN NAMES VISIBLE: False; PIN NUMBERS VISIBLE: False; SAVECOUNT: 1; TIME: 16:59:57; TYPE: GCM21BR71H105K; UPDATEDATE: 2018/09/12; UPDATETIME: 16:59:57; UPDATEUSER: w20070dm; VAL1: 1uF(K); VAL2: 50V; VAL3: GCM21BR71H105K
C46 = C: AUTHOR: w20070dm; COMMENT: Chip-Capacitor(X7R),1uF-K,50V; COMPCOMMENT: 2012; COMPONENTNAME: C_C; COMPONENTTYPE: 4; DATE: 2018/09/12; INSTANCENAME: I90955; MAKER: Murata; NUMBER DEVICES IN PACKAGE: 1; PIN NAMES ROTATE: True; PIN NAMES VISIBLE: False; PIN NUMBERS VISIBLE: False; SAVECOUNT: 1; TIME: 16:59:57; TYPE: GCM21BR71H105K; UPDATEDATE: 2018/09/12; UPDATETIME: 16:59:57; UPDATEUSER: w20070dm; VAL1: 1uF(K); VAL2: 50V; VAL3: GCM21BR71H105K
C61 = C: AUTHOR: w20070dm; COMMENT: Chip-Capacitor(X7R),1uF-K,50V; COMPCOMMENT: 2012; COMPONENTNAME: C_C; COMPONENTTYPE: 4; DATE: 2018/09/12; INSTANCENAME: I55413; MAKER: Murata; NUMBER DEVICES IN PACKAGE: 1; PIN NAMES ROTATE: True; PIN NAMES VISIBLE: False; PIN NUMBERS VISIBLE: False; SAVECOUNT: 1; TIME: 16:59:57; TYPE: GCM21BR71H105K; UPDATEDATE: 2018/09/12; UPDATETIME: 16:59:57; UPDATEUSER: w20070dm; VAL1: 1uF(K); VAL2: 50V; VAL3: GCM21BR71H105K
C62 = C: AUTHOR: w20070dm; COMMENT: Chip-Capacitor(X7R),1uF-K,50V; COMPCOMMENT: 2012; COMPONENTNAME: C_C; COMPONENTTYPE: 4; DATE: 2018/09/12; INSTANCENAME: I36792; MAKER: Murata; NUMBER DEVICES IN PACKAGE: 1; PIN NAMES ROTATE: True; PIN NAMES VISIBLE: False; PIN NUMBERS VISIBLE: False; SAVECOUNT: 1; TIME: 16:59:57; TYPE: GCM21BR71H105K; UPDATEDATE: 2018/09/12; UPDATETIME: 16:59:57; UPDATEUSER: w20070dm; VAL1: 1uF(K); VAL2: 50V; VAL3: GCM21BR71H105K
C63 = C: AUTHOR: w20070dm; COMMENT: Chip-Capasitor(CH0),150pF-J,50V; COMPCOMMENT: 1005; COMPONENTNAME: C_C; COMPONENTTYPE: 4; DATE: 2018/09/12; INSTANCENAME: I36377; MAKER: MURATA; NUMBER DEVICES IN PACKAGE: 1; PIN NAMES ROTATE: True; PIN NAMES VISIBLE: False; PIN NUMBERS VISIBLE: False; SAVECOUNT: 1; TIME: 16:59:57; TYPE: GRM1552C1H151J; UPDATEDATE: 2018/09/12; UPDATETIME: 16:59:57; UPDATEUSER: w20070dm; VAL1: 150pF(J); VAL2: 50V; VAL3: GRM1552C1H151J
C64 = C: AUTHOR: w20070dm; COMMENT: Chip-Capasitor(CH0),6800pF-J,50V; COMPCOMMENT: 1608; COMPONENTNAME: C_C; COMPONENTTYPE: 4; DATE: 2018/09/12; INSTANCENAME: I36005; MAKER: MURATA; NUMBER DEVICES IN PACKAGE: 1; PIN NAMES ROTATE: True; PIN NAMES VISIBLE: False; PIN NUMBERS VISIBLE: False; SAVECOUNT: 1; TIME: 16:59:57; TYPE: GRM1882C1H682J; UPDATEDATE: 2018/09/12; UPDATETIME: 16:59:57; UPDATEUSER: w20070dm; VAL1: 6800pF(J); VAL2: 50V; VAL3: GRM1882C1H682J
C65 = C: AUTHOR: w20070dm; COMMENT: Chip-Capasitor(CH0),2200pF-J,50V; COMPCOMMENT: 1608; COMPONENTNAME: C_C; COMPONENTTYPE: 4; DATE: 2018/09/12; INSTANCENAME: I34854; MAKER: MURATA; NUMBER DEVICES IN PACKAGE: 1; PIN NAMES ROTATE: True; PIN NAMES VISIBLE: False; PIN NUMBERS VISIBLE: False; SAVECOUNT: 1; TIME: 16:59:57; TYPE: GRM1882C1H222J; UPDATEDATE: 2018/09/12; UPDATETIME: 16:59:57; UPDATEUSER: w20070dm; VAL1: 2200pF(J); VAL2: 50V; VAL3: GRM1882C1H222J
C66 = C: AUTHOR: w20070dm; COMMENT: Chip-Capacitor(X7R),1uF-K,50V; COMPCOMMENT: 2012; COMPONENTNAME: C_C; COMPONENTTYPE: 4; DATE: 2018/09/12; INSTANCENAME: I55902; MAKER: Murata; NUMBER DEVICES IN PACKAGE: 1; PIN NAMES ROTATE: True; PIN NAMES VISIBLE: False; PIN NUMBERS VISIBLE: False; SAVECOUNT: 1; TIME: 16:59:57; TYPE: GCM21BR71H105K; UPDATEDATE: 2018/09/12; UPDATETIME: 16:59:57; UPDATEUSER: w20070dm; VAL1: 1uF(K); VAL2: 50V; VAL3: GCM21BR71H105K
C67 = C: AUTHOR: w20070dm; COMMENT: Chip-Capacitor(X7R),1uF-K,50V; COMPCOMMENT: 2012; COMPONENTNAME: C_C; COMPONENTTYPE: 4; DATE: 2018/09/12; INSTANCENAME: I55952; MAKER: Murata; NUMBER DEVICES IN PACKAGE: 1; PIN NAMES ROTATE: True; PIN NAMES VISIBLE: False; PIN NUMBERS VISIBLE: False; SAVECOUNT: 1; TIME: 16:59:57; TYPE: GCM21BR71H105K; UPDATEDATE: 2018/09/12; UPDATETIME: 16:59:57; UPDATEUSER: w20070dm; VAL1: 1uF(K); VAL2: 50V; VAL3: GCM21BR71H105K
CN4 = CN5: AUTHOR: w20070dm; COMMENT: Pin-Header(5pin,PCB-Straight); COMPONENTNAME: PIN-HEADER_5x1_PIN-HEADER_5x1.Normal_package; COMPONENTTYPE: 4; DATE: 2018/09/12; FUNCTION: PIN-HEADER_5x1_PIN-HEADER_5x1.Normal_package; INSTANCENAME: I21634261; MAKER: HIROSE; NUMBER DEVICES IN PACKAGE: 1; PARTNAME: PIN-HEADER_5x1; PIN NAMES ROTATE: True; PIN NAMES VISIBLE: False; PIN NUMBERS VISIBLE: True; SAVECOUNT: 1; TIME: 16:59:57; UPDATEDATE: 2018/09/12; UPDATETIME: 16:59:57; UPDATEUSER: w20070dm
FB1 = L: AUTHOR: w20070dm; COMMENT: Ferrite-bead,DC1.4A; COMPONENTNAME: INDUCTOR_INDUCTOR; COMPONENTTYPE: 4; DATE: 2018/09/12; INSTANCENAME: I21939901; MAKER: MURATA; NUMBER DEVICES IN PACKAGE: 1; ORDER: 0; PARTNAME: INDUCTOR; PIN NAMES ROTATE: True; PIN NAMES VISIBLE: False; PIN NUMBERS VISIBLE: False; SAVECOUNT: 1; TIME: 16:59:57; TYPE: BLM18PG221SN1; UPDATEDATE: 2018/09/12; UPDATETIME: 16:59:57; UPDATEUSER: w20070dm; VAL3: BLM18PG221SN1
IC2 = TLP2767: COMMENT: Photo-Coupler(LED-in_Logic-out); COMPONENTNAME: TLP2767_TLP2767.Normal_package; COMPONENTTYPE: 4; FUNCTION: TLP2767_TLP2767.Normal_package; INSTANCENAME: I79931; MAKER: Toshiba; NUMBER DEVICES IN PACKAGE: 1; PIN NAMES ROTATE: True; PIN NAMES VISIBLE: False; PIN NUMBERS VISIBLE: True; USERCOMPTEXT3: TOSHIBA
IC3 = TLP2767: COMMENT: Photo-Coupler(LED-in_Logic-out); COMPONENTNAME: TLP2767_TLP2767.Normal_package; COMPONENTTYPE: 4; FUNCTION: TLP2767_TLP2767.Normal_package; INSTANCENAME: I80693; MAKER: Toshiba; NUMBER DEVICES IN PACKAGE: 1; PIN NAMES ROTATE: True; PIN NAMES VISIBLE: False; PIN NUMBERS VISIBLE: True; USERCOMPTEXT3: TOSHIBA
IC4 = TLP785: COMMENT: Photo-Coupler(LED-Tr,80V50mA); COMPONENTNAME: TLP291_TLP291.Normal_package; COMPONENTTYPE: 4; FUNCTION: TLP291_TLP291.Normal_package; INSTANCENAME: I21316553; MAKER: Toshiba; NUMBER DEVICES IN PACKAGE: 1; PARTNAME: TLP291; PIN NAMES ROTATE: True; PIN NAMES VISIBLE: False; PIN NUMBERS VISIBLE: True; USERCOMPTEXT3: TOSHIBA
IC5 = L27523: COMMENT: Gate-Driver(Dual,Inverting); COMPONENTNAME: UCC27523D_UCC27523D.Normal_package; COMPONENTTYPE: 4; FUNCTION: UCC27523D_UCC27523D.Normal_package; INSTANCENAME: I87495; MAKER: T.I.; NUMBER DEVICES IN PACKAGE: 1; PIN NAMES ROTATE: True; PIN NAMES VISIBLE: True; PIN NUMBERS VISIBLE: True; TYPE: UCC27523DSD
IC7 = L4805_1: COMPONENTTYPE: 4; CaptureCellPackProp: L4805_1A; PARTNAME: ADA4805-2ARM; VAL3: ADA4805-2ARM
IC8 = L280: COMPONENTTYPE: 4; PARTNAME: ADR280ART; VAL3: ADR280ART
J1 = CN2: AUTHOR: w20070dm; COMMENT: PIN-HEADER,2pin-Straight; COMPONENTNAME: PIN-HEADER_2x1(A)_PIN-HEADER_2x1(A); COMPONENTTYPE: 4; DATE: 2018/09/12; INSTANCENAME: I39896; MAKER: HONDA; NOTMOUNT: NOT MOUNT; NUMBER DEVICES IN PACKAGE: 1; PARTNAME: PIN-HEADER_2x1(A); PIN NAMES ROTATE: True; PIN NAMES VISIBLE: False; PIN NUMBERS VISIBLE: True; SAVECOUNT: 1; TIME: 16:59:57; TYPE: FFC-2AMEP1; UPDATEDATE: 2018/09/12; UPDATETIME: 16:59:57; UPDATEUSER: w20070dm; VAL3: FFC-2AMEP1
R36 = R: AUTHOR: w20070dm; COMMENT: Chip-Resistor,470ohm-F(100ppm),1/10W; COMPCOMMENT: 1608; COMPONENTNAME: R_R; COMPONENTTYPE: 4; DATE: 2018/09/12; INSTANCENAME: I80721; MAKER: KOA; NUMBER DEVICES IN PACKAGE: 1; PIN NAMES ROTATE: True; PIN NAMES VISIBLE: False; PIN NUMBERS VISIBLE: False; SAVECOUNT: 1; TIME: 16:59:57; TYPE: RK73H1JTTD4700F; UPDATEDATE: 2018/09/12; UPDATETIME: 16:59:57; UPDATEUSER: w20070dm; VAL1: 470(F); VAL2: 1/10W; VAL3: RK73H1JTTD4700F
R37 = R: AUTHOR: w20070dm; COMMENT: Chip-Resistor,470ohm-F(100ppm),1/10W; COMPCOMMENT: 1608; COMPONENTNAME: R_R; COMPONENTTYPE: 4; DATE: 2018/09/12; INSTANCENAME: I105808; MAKER: KOA; NUMBER DEVICES IN PACKAGE: 1; PIN NAMES ROTATE: True; PIN NAMES VISIBLE: False; PIN NUMBERS VISIBLE: False; SAVECOUNT: 1; TIME: 16:59:57; TYPE: RK73H1JTTD4700F; UPDATEDATE: 2018/09/12; UPDATETIME: 16:59:57; UPDATEUSER: w20070dm; VAL1: 470(F); VAL2: 1/10W; VAL3: RK73H1JTTD4700F
R38 = R: AUTHOR: w20070dm; COMMENT: Chip-Resistor,470ohm-F(100ppm),1/10W; COMPCOMMENT: 1608; COMPONENTNAME: R_R; COMPONENTTYPE: 4; DATE: 2018/09/12; INSTANCENAME: I105857; MAKER: KOA; NUMBER DEVICES IN PACKAGE: 1; PIN NAMES ROTATE: True; PIN NAMES VISIBLE: False; PIN NUMBERS VISIBLE: False; SAVECOUNT: 1; TIME: 16:59:57; TYPE: RK73H1JTTD4700F; UPDATEDATE: 2018/09/12; UPDATETIME: 16:59:57; UPDATEUSER: w20070dm; VAL1: 470(F); VAL2: 1/10W; VAL3: RK73H1JTTD4700F
R39 = R: AUTHOR: w20070dm; COMMENT: Chip-Resistor,470ohm-F(100ppm),1/10W; COMPCOMMENT: 1608; COMPONENTNAME: R_R; COMPONENTTYPE: 4; DATE: 2018/09/12; INSTANCENAME: I106383; MAKER: KOA; NUMBER DEVICES IN PACKAGE: 1; PIN NAMES ROTATE: True; PIN NAMES VISIBLE: False; PIN NUMBERS VISIBLE: False; SAVECOUNT: 1; TIME: 16:59:57; TYPE: RK73H1JTTD4700F; UPDATEDATE: 2018/09/12; UPDATETIME: 16:59:57; UPDATEUSER: w20070dm; VAL1: 470(F); VAL2: 1/10W; VAL3: RK73H1JTTD4700F
R52 = R: AUTHOR: w20070dm; COMMENT: Chip-Resistor,22ohm-F(100ppm),1/10W; COMPCOMMENT: 1608; COMPONENTNAME: R_R; COMPONENTTYPE: 4; DATE: 2018/09/12; INSTANCENAME: I53738; MAKER: KOA; NUMBER DEVICES IN PACKAGE: 1; PIN NAMES ROTATE: True; PIN NAMES VISIBLE: False; PIN NUMBERS VISIBLE: False; SAVECOUNT: 1; TIME: 16:59:57; TYPE: RK73H1JTTD22R0F; UPDATEDATE: 2018/09/12; UPDATETIME: 16:59:57; UPDATEUSER: w20070dm; VAL1: 22(F); VAL3: RK73H1JTTD22R0F
R53 = R: AUTHOR: w20070dm; COMMENT: Chip-Resistor,22ohm-F(100ppm),1/10W; COMPCOMMENT: 1608; COMPONENTNAME: R_R; COMPONENTTYPE: 4; DATE: 2018/09/12; INSTANCENAME: I53644; MAKER: KOA; NUMBER DEVICES IN PACKAGE: 1; PIN NAMES ROTATE: True; PIN NAMES VISIBLE: False; PIN NUMBERS VISIBLE: False; SAVECOUNT: 1; TIME: 16:59:57; TYPE: RK73H1JTTD22R0F; UPDATEDATE: 2018/09/12; UPDATETIME: 16:59:57; UPDATEUSER: w20070dm; VAL1: 22(F); VAL3: RK73H1JTTD22R0F
R54 = R: AUTHOR: w20070dm; COMMENT: Chip-Resistor,22k-F(100ppm),1/10W; COMPCOMMENT: 1608; COMPONENTNAME: R_R; COMPONENTTYPE: 4; DATE: 2018/09/12; INSTANCENAME: I33721; MAKER: KOA; NUMBER DEVICES IN PACKAGE: 1; PIN NAMES ROTATE: True; PIN NAMES VISIBLE: False; PIN NUMBERS VISIBLE: False; SAVECOUNT: 1; TIME: 16:59:57; TYPE: RK73H1JTTD2202F; UPDATEDATE: 2018/09/12; UPDATETIME: 16:59:57; UPDATEUSER: w20070dm; VAL1: 22k(F); VAL3: RK73H1JTTD2202F
R55 = R: AUTHOR: w20070dm; COMMENT: Chip-Resistor,22k-F(100ppm),1/10W; COMPCOMMENT: 1608; COMPONENTNAME: R_R; COMPONENTTYPE: 4; DATE: 2018/09/12; INSTANCENAME: I33880; MAKER: KOA; NUMBER DEVICES IN PACKAGE: 1; PIN NAMES ROTATE: True; PIN NAMES VISIBLE: False; PIN NUMBERS VISIBLE: False; SAVECOUNT: 1; TIME: 16:59:57; TYPE: RK73H1JTTD2202F; UPDATEDATE: 2018/09/12; UPDATETIME: 16:59:57; UPDATEUSER: w20070dm; VAL1: 22k(F); VAL3: RK73H1JTTD2202F
R56 = R: AUTHOR: w20070dm; COMMENT: Chip-Resistor,22k-F(100ppm),1/10W; COMPCOMMENT: 1608; COMPONENTNAME: R_R; COMPONENTTYPE: 4; DATE: 2018/09/12; INSTANCENAME: I33649; MAKER: KOA; NUMBER DEVICES IN PACKAGE: 1; PIN NAMES ROTATE: True; PIN NAMES VISIBLE: False; PIN NUMBERS VISIBLE: False; SAVECOUNT: 1; TIME: 16:59:57; TYPE: RK73H1JTTD2202F; UPDATEDATE: 2018/09/12; UPDATETIME: 16:59:57; UPDATEUSER: w20070dm; VAL1: 22k(F); VAL3: RK73H1JTTD2202F
R57 = R: AUTHOR: w20070dm; COMMENT: Chip-Resistor,22k-F(100ppm),1/10W; COMPCOMMENT: 1608; COMPONENTNAME: R_R; COMPONENTTYPE: 4; DATE: 2018/09/12; INSTANCENAME: I33916; MAKER: KOA; NUMBER DEVICES IN PACKAGE: 1; PIN NAMES ROTATE: True; PIN NAMES VISIBLE: False; PIN NUMBERS VISIBLE: False; SAVECOUNT: 1; TIME: 16:59:57; TYPE: RK73H1JTTD2202F; UPDATEDATE: 2018/09/12; UPDATETIME: 16:59:57; UPDATEUSER: w20070dm; VAL1: 22k(F); VAL3: RK73H1JTTD2202F
R58 = R: AUTHOR: w20070dm; COMMENT: Chip-Resistor,560ohm-F(100ppm),1/10W; COMPCOMMENT: 1608; COMPONENTNAME: R_R; COMPONENTTYPE: 4; DATE: 2018/09/12; INSTANCENAME: I34582; MAKER: KOA; NUMBER DEVICES IN PACKAGE: 1; PIN NAMES ROTATE: True; PIN NAMES VISIBLE: False; PIN NUMBERS VISIBLE: False; SAVECOUNT: 1; TIME: 16:59:57; TYPE: RK73H1JTTD5600F; UPDATEDATE: 2018/09/12; UPDATETIME: 16:59:57; UPDATEUSER: w20070dm; VAL1: 560(F); VAL3: RK73H1JTTD5600F
R59 = R: AUTHOR: w20070dm; COMMENT: Chip-Resistor,22k-F(100ppm),1/10W; COMPCOMMENT: 1608; COMPONENTNAME: R_R; COMPONENTTYPE: 4; DATE: 2018/09/12; INSTANCENAME: I34100; MAKER: KOA; NUMBER DEVICES IN PACKAGE: 1; PIN NAMES ROTATE: True; PIN NAMES VISIBLE: False; PIN NUMBERS VISIBLE: False; SAVECOUNT: 1; TIME: 16:59:57; TYPE: RK73H1JTTD2202F; UPDATEDATE: 2018/09/12; UPDATETIME: 16:59:57; UPDATEUSER: w20070dm; VAL1: 22k(F); VAL3: RK73H1JTTD2202F
R61 = R: AUTHOR: w20070dm; COMMENT: Chip-Resistor,20k-F(100ppm),1/10W; COMPCOMMENT: 1608; COMPONENTNAME: R_R; COMPONENTTYPE: 4; DATE: 2018/09/12; INSTANCENAME: I34438; MAKER: KOA; NUMBER DEVICES IN PACKAGE: 1; PIN NAMES ROTATE: True; PIN NAMES VISIBLE: False; PIN NUMBERS VISIBLE: False; SAVECOUNT: 1; TIME: 16:59:57; TYPE: RK73H1JTTD2002F; UPDATEDATE: 2018/09/12; UPDATETIME: 16:59:57; UPDATEUSER: w20070dm; VAL1: 20k(F); VAL3: RK73H1JTTD2002F
R62 = R: AUTHOR: w20070dm; COMMENT: Chip-Resistor,22k-F(100ppm),1/10W; COMPCOMMENT: 1608; COMPONENTNAME: R_R; COMPONENTTYPE: 4; DATE: 2018/09/12; INSTANCENAME: I36079; MAKER: KOA; NUMBER DEVICES IN PACKAGE: 1; PIN NAMES ROTATE: True; PIN NAMES VISIBLE: False; PIN NUMBERS VISIBLE: False; SAVECOUNT: 1; TIME: 16:59:57; TYPE: RK73H1JTTD2202F; UPDATEDATE: 2018/09/12; UPDATETIME: 16:59:57; UPDATEUSER: w20070dm; VAL1: 22k(F); VAL3: RK73H1JTTD2202F
R63 = R: AUTHOR: w20070dm; COMMENT: Chip-Resistor,22k-F(100ppm),1/10W; COMPCOMMENT: 1608; COMPONENTNAME: R_R; COMPONENTTYPE: 4; DATE: 2018/09/12; INSTANCENAME: I37146; MAKER: KOA; NUMBER DEVICES IN PACKAGE: 1; PIN NAMES ROTATE: True; PIN NAMES VISIBLE: False; PIN NUMBERS VISIBLE: False; SAVECOUNT: 1; TIME: 16:59:57; TYPE: RK73H1JTTD2202F; UPDATEDATE: 2018/09/12; UPDATETIME: 16:59:57; UPDATEUSER: w20070dm; VAL1: 22k(F); VAL3: RK73H1JTTD2202F
R64 R65 = R: AUTHOR: w20070dm; COMMENT: Chip-Resistor,2k0-F(100ppm),1/10W; COMPCOMMENT: 1608; COMPONENTNAME: R_R; COMPONENTTYPE: 4; DATE: 2018/09/12; INSTANCENAME: I32754; MAKER: KOA; NUMBER DEVICES IN PACKAGE: 1; PIN NAMES ROTATE: True; PIN NAMES VISIBLE: False; PIN NUMBERS VISIBLE: False; SAVECOUNT: 1; TIME: 16:59:57; TYPE: RK73H1JTTD2001F; UPDATEDATE: 2018/09/12; UPDATETIME: 16:59:57; UPDATEUSER: w20070dm; VAL1: 2K(F); VAL3: RK73H1JTTD2001F
U?#4 = WAKU_DEF100_2018: COMPONENTTYPE: 2; DATE: 2018-11-02; DRAWINGNUMBER: RD040-SCHEMATIC-01; FUNCTION: Photocoupler&Feedback; REVISION: 00; SAVEAREA0: -45080,-4508,463680,304612; SHEETNUMBER: 4/4; TIME: 13:53:51; TITLE: 1.2V/100A Output DC-DC Converter / Compliant with 48V Bus Voltage; UPDATEDATE: 2018/11/05; UPDATETIME: 09:58:42

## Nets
0_5V: C32.1 C34.1 IC2.6 IC3.6
0_10V: C42.1 C46.2 IC5.1 IC5.6 IC5.8 IC6.1 IC6.5 Q4.3
0_GND: C44.2 C46.1 IC5.3 IC6.2 J1.2
I_10V: C13.1 Q3.3 ; also on sheet 3
LGND: C61.2 C62.2 C66.2 C67.1 CN4.3 IC7.4 IC8.3 J1.1 R65.1
O_5V: C44.1 FB1.2 IC6.4
O_GND: C14.2 C32.2 C34.2 C41.2 C42.2 C48.2 C52.2 C53.2 C54.2 C55.2 C56.2 C57.2 C58.2 CN3.1 CN4.1 D10.A D11.A IC2.4 IC3.4 Q5.S Q6.S Q7.S Q8.S R53.2
OUT+: C52.1 C53.1 C54.1 C55.1 C56.1 C57.1 C58.1 CN2.1 CN4.5 L2.2 L3.2 R52.2
PN: C12.2 C13.2 C14.1 D7.A D8.A R38.2 R39.2 ; also on sheet 3 4
N04057: T1.1 ; also on sheet 4
N10150: IC4.3 ; also on sheet 3
N13908: IC4.4 ; also on sheet 3
N14012: C31.2 R36.1 ; also on sheet 3
N14069: C33.2 R37.1 ; also on sheet 3
N17106: Q5.G R44.1
N17193: Q6.G R45.1
N17255: Q7.G R46.1
N17317: Q8.G R47.1
N17411: C51.1 Q5.D Q6.D T1.S1 T1.S2
N17449: Q7.D Q8.D R48.1 T1.P1 T1.P2
N17555: IC5.7 R44.2 R45.2
N17605: IC5.5 R46.2 R47.2
N20539: L2.1 L3.1 T1.Q1 T1.Q2 T1.Q3 T1.Q4
N24537: D6.A D7.C T1.3
N25173: C11.2 C12.1 T1.4
N25453: C11.1 D6.C Q3.2 R11.2
N25757: D8.C Q3.1 R11.1
N27553: T1.2 ; also on sheet 4
N27715: C51.2 R48.2
N28004: C41.1 C47.1 D9.C Q4.2 R43.2
N28016: D11.C Q4.1 R43.1
N32717: C61.1 C62.1 C66.1 FB1.1 IC4.1 IC7.8 IC8.1
N32808: IC4.2 R64.1
N32839: C63.2 IC7.1 R62.1 R64.2
N33727: IC7.7 R56.1 R58.2 R59.2
N33769: IC7.6 R54.1 R56.2
N33837: IC7.5 R55.1 R57.2
N33896: C67.2 IC8.2 R57.1 R63.2
N34516: C63.1 C64.1 C65.2 IC7.2 R59.1 R61.2
N35926: C65.1 R58.1
N36200: C64.2 R62.2
N37152: IC7.3 R63.1
N53493: CN4.2 R53.1 R54.2
N53543: CN4.4 R52.1 R55.2
N56552: R61.1 R65.2
N80775: IC2.3 R38.1
N80936: C31.1 IC2.1 R36.2
N81048: C33.1 IC3.1 R37.2
N87643: IC2.5 IC5.2
N87699: IC3.5 IC5.4
N106339: IC3.3 R39.1
N115099: D9.A D10.C T1.6
N115166: C47.2 C48.1 T1.7

Not connected (* = marked no-connect by the designer): IC2 2; IC3 2; IC6 3; T1 5 8 9 10

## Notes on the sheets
sheet 1
- V+_MONIT
- SENSE+
- SIELD
- SENSE-
- V-_MONIT
- Ref_1.2V
sheet 2
- Option
- 1T
- x2
- 8T
- 1T
- 1T
- 1T
- x4
- 3T
- 3T
- x2
